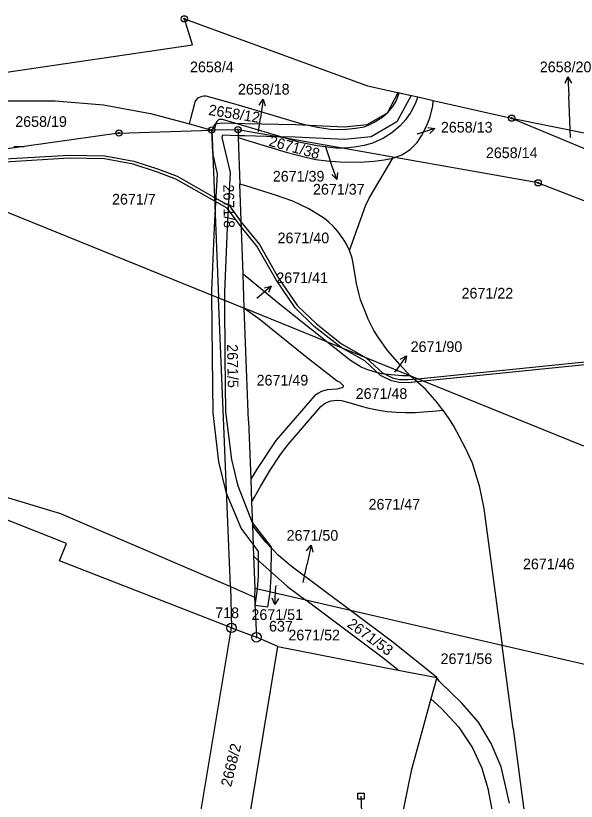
# Model space of a CAD drawing. Extents: x -755819 to -753140, y -1169796 to -1166000.
# Drawn here: x -754380.1 to -754290.9, y -1168245.5 to -1168120.5 of the extents above; entities that cross this region are included whole.
import ezdxf

# ---------------------------------------------------------------- set-up
doc = ezdxf.new("R2010")
doc.units = 0
for name, color, linetype in [('Vrstva 1', 7, 'Continuous'), ('Vrstva 12', 7, 'Continuous'), ('Vrstva 13', 7, 'Continuous'), ('Vrstva 16', 7, 'Continuous'), ('Vrstva 17', 7, 'Continuous'), ('Vrstva 18', 7, 'Continuous'), ('Vrstva 24', 7, 'Continuous'), ('Vrstva 26', 7, 'Continuous'), ('Vrstva 27', 7, 'Continuous'), ('Vrstva 4', 7, 'Continuous')]:
    doc.layers.add(name, color=color, linetype=linetype)

msp = doc.modelspace()

# ---------------------------------------------------------------- linework, layer by layer
at = {"layer": 'Vrstva 1'}
for p, q in [((-754319.59, -1168134.04), (-754319.11, -1168132.73)), ((-754382.31, -1168133.99), (-754373.85, -1168134)), ((-754373.85, -1168134), (-754366.18, -1168134.65)), ((-754351.68, -1168134.59), (-754351.55, -1168134.15)), ((-754351.55, -1168134.15), (-754351.36, -1168133.83)), ((-754351.36, -1168133.83), (-754351.07, -1168133.54)), ((-754351.07, -1168133.54), (-754350.74, -1168133.35)), ((-754350.74, -1168133.35), (-754350.45, -1168133.25)), ((-754350.45, -1168133.25), (-754350.18, -1168133.21)), ((-754350.18, -1168133.21), (-754349.89, -1168133.22)), ((-754349.89, -1168133.22), (-754344.72, -1168134.67)), ((-754320.12, -1168134.89), (-754319.59, -1168134.04)), ((-754316.15, -1168133.4), (-754316.57, -1168134.47)), ((-754313.75, -1168134.85), (-754313.67, -1168133.96)), ((-754366.18, -1168134.65), (-754358.7, -1168136.04)), ((-754352.27, -1168136.85), (-754351.68, -1168134.59)), ((-754344.72, -1168134.67), (-754334.58, -1168137.67)), ((-754320.92, -1168135.85), (-754320.12, -1168134.89)), ((-754316.57, -1168134.47), (-754317.25, -1168135.83)), ((-754314.23, -1168136.73), (-754313.75, -1168134.85)), ((-754358.7, -1168136.04), (-754352.46, -1168137.65)), ((-754323.07, -1168137.42), (-754321.87, -1168136.64)), ((-754321.87, -1168136.64), (-754320.92, -1168135.85)), ((-754317.25, -1168135.83), (-754318.07, -1168137.05)), ((-754352.46, -1168137.65), (-754352.27, -1168136.85)), ((-754352.46, -1168137.65), (-754348.93, -1168138.67)), ((-754348.29, -1168137.61), (-754348.54, -1168138.67)), ((-754348.24, -1168137.47), (-754348.29, -1168137.61)), ((-754348.14, -1168137.31), (-754348.24, -1168137.47)), ((-754348.02, -1168137.18), (-754348.14, -1168137.31)), ((-754347.9, -1168137.08), (-754348.02, -1168137.18)), ((-754347.72, -1168136.99), (-754347.9, -1168137.08)), ((-754347.47, -1168136.96), (-754347.72, -1168136.99)), ((-754347.23, -1168136.98), (-754347.47, -1168136.96)), ((-754337.18, -1168139.96), (-754347.23, -1168136.98)), ((-754334.58, -1168137.67), (-754332.1, -1168138.23)), ((-754324.67, -1168138.14), (-754323.87, -1168137.82)), ((-754323.87, -1168137.82), (-754323.07, -1168137.42)), ((-754318.07, -1168137.05), (-754318.92, -1168137.98)), ((-754315.53, -1168139.6), (-754314.69, -1168137.96)), ((-754314.69, -1168137.96), (-754314.23, -1168136.73)), ((-754301.2, -1168136.77), (-754285.23, -1168143.41)), ((-754363.71, -1168139.14), (-754378.79, -1168141.26)), ((-754363.71, -1168139.14), (-754348.93, -1168138.67)), ((-754348.93, -1168138.67), (-754347.83, -1168165.39)), ((-754348.54, -1168138.67), (-754348.93, -1168138.67)), ((-754344.74, -1168138.62), (-754348.54, -1168138.67)), ((-754337.18, -1168139.96), (-754344.74, -1168138.62)), ((-754344.74, -1168138.62), (-754344.7, -1168139.87)), ((-754332.1, -1168138.23), (-754329.7, -1168138.58)), ((-754329.7, -1168138.58), (-754327.51, -1168138.55)), ((-754327.51, -1168138.55), (-754326.01, -1168138.39)), ((-754326.01, -1168138.39), (-754324.67, -1168138.14)), ((-754320.24, -1168139.1), (-754321.57, -1168139.97)), ((-754318.92, -1168137.98), (-754320.24, -1168139.1)), ((-754344.7, -1168139.87), (-754342.88, -1168140.41)), ((-754344.7, -1168139.87), (-754344.44, -1168147.26)), ((-754342.88, -1168140.41), (-754337.11, -1168142.19)), ((-754328.18, -1168141.55), (-754337.18, -1168139.96)), ((-754335.08, -1168140.58), (-754337.18, -1168139.96)), ((-754321.57, -1168139.97), (-754323.32, -1168140.76)), ((-754316.24, -1168140.66), (-754315.53, -1168139.6)), ((-754378.79, -1168141.26), (-754385.44, -1168142.2)), ((-754380.44, -1168141.3), (-754378.79, -1168141.26)), ((-754332.16, -1168141.2), (-754335.08, -1168140.58)), ((-754329.2, -1168141.56), (-754332.16, -1168141.2)), ((-754328.18, -1168141.55), (-754329.2, -1168141.56)), ((-754327.77, -1168141.54), (-754328.18, -1168141.55)), ((-754319.78, -1168143.03), (-754328.18, -1168141.55)), ((-754326.21, -1168141.4), (-754327.77, -1168141.54)), ((-754324.68, -1168141.13), (-754326.21, -1168141.4)), ((-754323.32, -1168140.76), (-754324.68, -1168141.13)), ((-754317.35, -1168141.77), (-754316.24, -1168140.66)), ((-754337.11, -1168142.19), (-754333.81, -1168143.04)), ((-754319.78, -1168143.03), (-754318.66, -1168142.62)), ((-754318.66, -1168142.62), (-754317.35, -1168141.77)), ((-754333.81, -1168143.04), (-754332.35, -1168143.33)), ((-754332.35, -1168143.33), (-754330.6, -1168143.58)), ((-754330.6, -1168143.58), (-754328.54, -1168143.75)), ((-754328.54, -1168143.75), (-754326.84, -1168143.79)), ((-754326.84, -1168143.79), (-754324.61, -1168143.75)), ((-754324.61, -1168143.75), (-754323.08, -1168143.63)), ((-754323.85, -1168149.51), (-754320.11, -1168143.16)), ((-754323.08, -1168143.63), (-754321.49, -1168143.42)), ((-754321.49, -1168143.42), (-754320.11, -1168143.16)), ((-754320.11, -1168143.16), (-754319.78, -1168143.03)), ((-754296.97, -1168147.07), (-754319.78, -1168143.03)), ((-754399.92, -1168144.24), (-754347.83, -1168165.39)), ((-754343.53, -1168147.53), (-754344.44, -1168147.26)), ((-754343.94, -1168161.59), (-754344.44, -1168147.26)), ((-754338.78, -1168149.02), (-754343.53, -1168147.53)), ((-754296.97, -1168147.07), (-754280.8, -1168153.37)), ((-754336.04, -1168149.99), (-754338.78, -1168149.02)), ((-754333.48, -1168151.2), (-754336.04, -1168149.99)), ((-754324.46, -1168150.75), (-754323.85, -1168149.51)), ((-754330.99, -1168152.77), (-754333.48, -1168151.2)), ((-754326.98, -1168157.84), (-754324.46, -1168150.75)), ((-754330.29, -1168153.35), (-754330.99, -1168152.77)), ((-754329.61, -1168153.99), (-754330.29, -1168153.35)), ((-754328.87, -1168154.81), (-754329.61, -1168153.99)), ((-754328, -1168155.99), (-754328.87, -1168154.81)), ((-754327.47, -1168156.82), (-754328, -1168155.99)), ((-754326.98, -1168157.84), (-754327.47, -1168156.82)), ((-754326.58, -1168159.06), (-754326.98, -1168157.84)), ((-754326.37, -1168160.2), (-754326.58, -1168159.06)), ((-754325.89, -1168163.07), (-754326.37, -1168160.2)), ((-754338.39, -1168166.17), (-754343.94, -1168161.59)), ((-754343.75, -1168167.04), (-754343.94, -1168161.59)), ((-754325.48, -1168164.84), (-754325.89, -1168163.07)), ((-754345.95, -1168211.35), (-754347.83, -1168165.39)), ((-754347.83, -1168165.39), (-754347.17, -1168165.66)), ((-754325.24, -1168165.69), (-754325.48, -1168164.84)), ((-754347.17, -1168165.66), (-754343.75, -1168167.04)), ((-754330.62, -1168172.37), (-754338.39, -1168166.17)), ((-754324.95, -1168166.48), (-754325.24, -1168165.69)), ((-754324.47, -1168167.68), (-754324.95, -1168166.48)), ((-754330.62, -1168172.37), (-754343.75, -1168167.04)), ((-754343.75, -1168167.04), (-754341.46, -1168168.69)), ((-754343.06, -1168184.98), (-754343.75, -1168167.04)), ((-754324.01, -1168168.8), (-754324.47, -1168167.68)), ((-754341.46, -1168168.69), (-754333.72, -1168174.88)), ((-754323.15, -1168170.56), (-754324.01, -1168168.8)), ((-754322.32, -1168171.8), (-754323.15, -1168170.56)), ((-754317.32, -1168177.77), (-754330.62, -1168172.37)), ((-754326.86, -1168175.37), (-754330.62, -1168172.37)), ((-754320.92, -1168173.79), (-754322.32, -1168171.8)), ((-754319.74, -1168175.15), (-754320.92, -1168173.79)), ((-754333.72, -1168174.88), (-754328.98, -1168178.58)), ((-754325.15, -1168176.4), (-754326.86, -1168175.37)), ((-754319.04, -1168175.96), (-754319.74, -1168175.15)), ((-754324.08, -1168176.85), (-754325.15, -1168176.4)), ((-754317.32, -1168177.77), (-754319.04, -1168175.96)), ((-754323.24, -1168177.13), (-754324.08, -1168176.85)), ((-754321.87, -1168177.46), (-754323.24, -1168177.13)), ((-754320.44, -1168177.64), (-754321.87, -1168177.46)), ((-754318.58, -1168177.77), (-754320.44, -1168177.64)), ((-754317.32, -1168177.77), (-754318.58, -1168177.77)), ((-754289.7, -1168188.98), (-754317.32, -1168177.77)), ((-754314.89, -1168179.91), (-754317.32, -1168177.77)), ((-754328.98, -1168178.58), (-754328.55, -1168178.83)), ((-754328.55, -1168178.83), (-754328.16, -1168179.17)), ((-754328.16, -1168179.17), (-754328, -1168179.34)), ((-754331.44, -1168180.29), (-754332.02, -1168180.59)), ((-754330.58, -1168180.03), (-754331.44, -1168180.29)), ((-754329.79, -1168179.95), (-754330.58, -1168180.03)), ((-754329.03, -1168179.91), (-754329.79, -1168179.95)), ((-754328.45, -1168179.78), (-754329.03, -1168179.91)), ((-754328.18, -1168179.69), (-754328.45, -1168179.78)), ((-754328.03, -1168179.53), (-754328.18, -1168179.69)), ((-754328, -1168179.34), (-754328.03, -1168179.53)), ((-754313.06, -1168182.03), (-754314.89, -1168179.91)), ((-754332.55, -1168180.96), (-754338.73, -1168188.1)), ((-754332.02, -1168180.59), (-754332.55, -1168180.96)), ((-754329.92, -1168181.76), (-754329.08, -1168181.66)), ((-754329.08, -1168181.66), (-754328.28, -1168181.75)), ((-754336.76, -1168188.73), (-754331.58, -1168182.67)), ((-754331.58, -1168182.67), (-754330.82, -1168182.11)), ((-754330.82, -1168182.11), (-754329.92, -1168181.76)), ((-754328.28, -1168181.75), (-754326.39, -1168182.26)), ((-754326.39, -1168182.26), (-754325.14, -1168182.63)), ((-754325.14, -1168182.63), (-754323.9, -1168182.94)), ((-754323.9, -1168182.94), (-754322.6, -1168183.2)), ((-754312.15, -1168183.25), (-754313.06, -1168182.03)), ((-754322.6, -1168183.2), (-754321.03, -1168183.45)), ((-754321.03, -1168183.45), (-754319.52, -1168183.58)), ((-754319.52, -1168183.58), (-754318.15, -1168183.63)), ((-754318.15, -1168183.63), (-754316.57, -1168183.62)), ((-754316.57, -1168183.62), (-754315.22, -1168183.54)), ((-754315.22, -1168183.54), (-754313.08, -1168183.38)), ((-754313.08, -1168183.38), (-754312.15, -1168183.25)), ((-754312.15, -1168183.25), (-754311.2, -1168184.65)), ((-754343.06, -1168184.98), (-754342.72, -1168194.26)), ((-754311.2, -1168184.65), (-754310.4, -1168185.88)), ((-754310.4, -1168185.88), (-754308.58, -1168189.25)), ((-754338.73, -1168188.1), (-754341.77, -1168192.66)), ((-754337.96, -1168190.34), (-754336.76, -1168188.73)), ((-754339.61, -1168192.83), (-754337.96, -1168190.34)), ((-754308.58, -1168189.25), (-754307.46, -1168191.66)), ((-754307.46, -1168191.66), (-754306.35, -1168195.3)), ((-754341.77, -1168192.66), (-754342.72, -1168194.26)), ((-754341.15, -1168195.42), (-754339.61, -1168192.83)), ((-754342.72, -1168194.26), (-754342.59, -1168197.93)), ((-754342.13, -1168197.14), (-754341.15, -1168195.42)), ((-754306.35, -1168195.3), (-754305.6, -1168198.94)), ((-754384.53, -1168196.24), (-754373, -1168199.71)), ((-754342.59, -1168197.93), (-754342.13, -1168197.14)), ((-754342.59, -1168197.93), (-754342.45, -1168201.58)), ((-754372.07, -1168204.5), (-754385.48, -1168199.21)), ((-754305.6, -1168198.94), (-754304.86, -1168204.47)), ((-754373, -1168199.71), (-754367.22, -1168202.2)), ((-754342.45, -1168201.58), (-754342.28, -1168206.53)), ((-754341.83, -1168202.4), (-754342.45, -1168201.58)), ((-754367.22, -1168202.2), (-754345.95, -1168211.35)), ((-754340.34, -1168204.3), (-754341.83, -1168202.4)), ((-754373.15, -1168207.26), (-754372.07, -1168204.5)), ((-754338.3, -1168206.4), (-754340.34, -1168204.3)), ((-754304.86, -1168204.47), (-754302.71, -1168220.73)), ((-754342.28, -1168206.53), (-754342.09, -1168211.67)), ((-754342.28, -1168206.53), (-754336.82, -1168211.4)), ((-754336.29, -1168208.11), (-754338.3, -1168206.4)), ((-754345.79, -1168217.93), (-754373.15, -1168207.26)), ((-754326.84, -1168215.18), (-754336.29, -1168208.11)), ((-754345.95, -1168211.35), (-754342.15, -1168213.05)), ((-754345.95, -1168211.35), (-754345.79, -1168217.93)), ((-754342.09, -1168211.67), (-754342.15, -1168213.05)), ((-754333.95, -1168213.54), (-754342.09, -1168211.67)), ((-754336.82, -1168211.4), (-754333.95, -1168213.54)), ((-754342.15, -1168213.05), (-754341.81, -1168219.43)), ((-754326.84, -1168215.18), (-754333.95, -1168213.54)), ((-754321.41, -1168222.9), (-754333.95, -1168213.54)), ((-754320.32, -1168220.06), (-754326.84, -1168215.18)), ((-754302.71, -1168220.73), (-754326.84, -1168215.18)), ((-754352.79, -1168259.85), (-754345.79, -1168217.93)), ((-754338.39, -1168220.89), (-754341.81, -1168219.43)), ((-754316.38, -1168223.18), (-754320.32, -1168220.06)), ((-754345.13, -1168261.31), (-754338.39, -1168220.89)), ((-754338.39, -1168220.89), (-754319.26, -1168224.64)), ((-754300.97, -1168233.96), (-754302.71, -1168220.73)), ((-754285.02, -1168224.8), (-754302.71, -1168220.73)), ((-754319.26, -1168224.64), (-754321.41, -1168222.9)), ((-754313.12, -1168225.84), (-754316.38, -1168223.18)), ((-754319.26, -1168224.64), (-754313.12, -1168225.84)), ((-754313.12, -1168225.84), (-754314.05, -1168229.21)), ((-754312.67, -1168226.46), (-754313.12, -1168225.84)), ((-754309.1, -1168229.92), (-754312.67, -1168226.46)), ((-754314.05, -1168229.21), (-754317.19, -1168240.66)), ((-754312.38, -1168230.77), (-754314.05, -1168229.21)), ((-754306.48, -1168232.94), (-754309.1, -1168229.92)), ((-754312.38, -1168230.77), (-754309.65, -1168233.68)), ((-754304.43, -1168236.35), (-754306.48, -1168232.94)), ((-754309.65, -1168233.68), (-754307.43, -1168237)), ((-754300.97, -1168233.96), (-754296.06, -1168271.2)), ((-754302.87, -1168240.04), (-754304.43, -1168236.35)), ((-754307.43, -1168237), (-754305.94, -1168240.25)), ((-754305.94, -1168240.25), (-754304.96, -1168243.52)), ((-754301.53, -1168245.85), (-754302.87, -1168240.04)), ((-754317.19, -1168240.66), (-754323.74, -1168272.33)), ((-754304.96, -1168243.52), (-754304.26, -1168247.44))]:
    msp.add_line(p, q, dxfattribs=at)
at = {"layer": 'Vrstva 12'}
msp.add_line((-754325.18, -1168244.72), (-754312.91, -1168527.7), dxfattribs=at)
at = {"layer": 'Vrstva 13'}
for p, q in [((-754352, -1168125.1), (-754353.28, -1168120.96)), ((-754353.28, -1168120.96), (-754324.14, -1168131.6)), ((-754415.92, -1168134.53), (-754352, -1168125.1)), ((-754324.14, -1168131.6), (-754319.11, -1168132.73)), ((-754319.11, -1168132.73), (-754316.15, -1168133.4)), ((-754316.15, -1168133.4), (-754313.67, -1168133.96)), ((-754313.67, -1168133.96), (-754301.2, -1168136.77)), ((-754301.2, -1168136.77), (-754288.58, -1168139.32))]:
    msp.add_line(p, q, dxfattribs=at)
at = {"layer": 'Vrstva 16'}
for p, q in [((-754292.22, -1168130.2), (-754292.1, -1168133.2)), ((-754340.77, -1168133.76), (-754341.18, -1168136.73)), ((-754291.83, -1168139.87), (-754292.1, -1168133.2)), ((-754341.49, -1168138.91), (-754341.18, -1168136.73)), ((-754313.41, -1168138.44), (-754316.27, -1168139.33)), ((-754330.88, -1168141.19), (-754330.02, -1168143.7)), ((-754329.04, -1168146.54), (-754330.02, -1168143.7)), ((-754339.46, -1168163.53), (-754341.75, -1168165.46)), ((-754317.95, -1168174.61), (-754319.68, -1168177.06)), ((-754319.77, -1168177.19), (-754319.68, -1168177.06)), ((-754333.13, -1168204.78), (-754333.75, -1168207.72)), ((-754334.39, -1168210.72), (-754333.75, -1168207.72)), ((-754338.87, -1168214.22), (-754338.73, -1168211.22))]:
    msp.add_line(p, q, dxfattribs=at)
for points in [[(-754292.68, -1168131.22), (-754292.22, -1168130.2), (-754291.68, -1168131.18)], [(-754341.4, -1168134.68), (-754340.77, -1168133.76), (-754340.41, -1168134.82)], [(-754314.51, -1168138.26), (-754313.41, -1168138.44), (-754314.21, -1168139.22)], [(-754328.9, -1168145.43), (-754329.04, -1168146.54), (-754329.84, -1168145.75)], [(-754340.54, -1168163.79), (-754339.46, -1168163.53), (-754339.9, -1168164.55)], [(-754318.93, -1168175.14), (-754317.95, -1168174.61), (-754318.12, -1168175.72)], [(-754333.83, -1168205.66), (-754333.13, -1168204.78), (-754332.85, -1168205.87)], [(-754338.33, -1168213.24), (-754338.87, -1168214.22), (-754339.33, -1168213.19)]]:
    msp.add_lwpolyline(points, dxfattribs=at)
at = {"layer": 'Vrstva 24'}
for centre, radius in [((-754353.28, -1168120.96), 0.5), ((-754353.28, -1168120.96), 0.1), ((-754301.2, -1168136.77), 0.5), ((-754301.2, -1168136.77), 0.1), ((-754363.71, -1168139.14), 0.5), ((-754363.71, -1168139.14), 0.1), ((-754348.93, -1168138.67), 0.5), ((-754348.93, -1168138.67), 0.1), ((-754344.74, -1168138.62), 0.5), ((-754344.74, -1168138.62), 0.1), ((-754296.97, -1168147.07), 0.5), ((-754296.97, -1168147.07), 0.1), ((-754345.79, -1168217.93), 0.75), ((-754345.79, -1168217.93), 0.1), ((-754341.81, -1168219.43), 0.75), ((-754341.81, -1168219.43), 0.1)]:
    msp.add_circle(centre, radius, dxfattribs=at)
at = {"layer": 'Vrstva 26'}
msp.add_lwpolyline([(-754325.68, -1168244.22), (-754324.68, -1168244.22), (-754324.68, -1168245.22), (-754325.68, -1168245.22)], close=True, dxfattribs=at)
at = {"layer": 'Vrstva 27'}
for p, q in [((-754320.97, -1168135.91), (-754319.24, -1168132.71)), ((-754319.24, -1168132.71), (-754317.21, -1168133.16)), ((-754317.21, -1168133.16), (-754319.47, -1168137.37)), ((-754324.21, -1168137.78), (-754320.97, -1168135.91)), ((-754348.93, -1168138.67), (-754348.38, -1168137.66)), ((-754348.38, -1168137.66), (-754347.36, -1168137.49)), ((-754347.36, -1168137.49), (-754343.68, -1168137.61)), ((-754343.68, -1168137.61), (-754335.59, -1168137.8)), ((-754335.59, -1168137.8), (-754327.84, -1168138.17)), ((-754327.84, -1168138.17), (-754324.21, -1168137.78)), ((-754319.47, -1168137.37), (-754323.57, -1168139.72)), ((-754348.78, -1168142.32), (-754348.93, -1168138.67)), ((-754347.22, -1168139.49), (-754347.3, -1168139.84)), ((-754347.3, -1168139.84), (-754346, -1168145.43)), ((-754344.71, -1168139.58), (-754347.22, -1168139.49)), ((-754343.74, -1168139.61), (-754344.71, -1168139.58)), ((-754338.44, -1168139.73), (-754343.74, -1168139.61)), ((-754335.67, -1168139.8), (-754338.44, -1168139.73)), ((-754327.78, -1168140.17), (-754335.67, -1168139.8)), ((-754323.57, -1168139.72), (-754327.78, -1168140.17)), ((-754381.88, -1168143.27), (-754371.64, -1168142.66)), ((-754371.64, -1168142.66), (-754365.95, -1168142.75)), ((-754365.95, -1168142.75), (-754361.33, -1168143.64)), ((-754348.02, -1168145.61), (-754348.78, -1168142.32)), ((-754371.63, -1168143.16), (-754381.87, -1168143.77)), ((-754366.01, -1168143.25), (-754371.63, -1168143.16)), ((-754361.45, -1168144.12), (-754366.01, -1168143.25)), ((-754357.55, -1168145.35), (-754361.45, -1168144.12)), ((-754361.33, -1168143.64), (-754357.39, -1168144.87)), ((-754354.63, -1168146.47), (-754357.55, -1168145.35)), ((-754357.39, -1168144.87), (-754354.41, -1168146.01)), ((-754346, -1168145.43), (-754346.49, -1168154.22)), ((-754348.46, -1168149.98), (-754354.63, -1168146.47)), ((-754354.41, -1168146.01), (-754348.49, -1168149.39)), ((-754348.38, -1168152.1), (-754348.02, -1168145.61)), ((-754348.49, -1168149.39), (-754346.13, -1168150.74)), ((-754346.47, -1168151.12), (-754348.46, -1168149.98)), ((-754344.2, -1168154.14), (-754346.47, -1168151.12)), ((-754346.13, -1168150.74), (-754344.23, -1168153.31)), ((-754348.49, -1168154.12), (-754348.38, -1168152.1)), ((-754348.9, -1168164.32), (-754348.49, -1168154.12)), ((-754346.49, -1168154.22), (-754346.9, -1168164.36)), ((-754344.23, -1168153.31), (-754341.35, -1168156.87)), ((-754341.77, -1168157.15), (-754344.2, -1168154.14)), ((-754338.7, -1168162.51), (-754341.77, -1168157.15)), ((-754341.35, -1168156.87), (-754338.28, -1168162.25)), ((-754335.64, -1168166.97), (-754338.7, -1168162.51)), ((-754338.28, -1168162.25), (-754335.26, -1168166.65)), ((-754348.9, -1168164.96), (-754348.9, -1168164.32)), ((-754348.83, -1168174.84), (-754348.9, -1168164.96)), ((-754346.9, -1168164.36), (-754346.89, -1168165.77)), ((-754346.89, -1168165.77), (-754346.83, -1168174.82)), ((-754335.26, -1168166.65), (-754332.28, -1168169.54)), ((-754332.61, -1168169.92), (-754335.64, -1168166.97)), ((-754328.32, -1168173.3), (-754332.61, -1168169.92)), ((-754332.28, -1168169.54), (-754328.25, -1168172.72)), ((-754328.25, -1168172.72), (-754324.35, -1168174.91)), ((-754324.54, -1168175.42), (-754328.32, -1168173.3)), ((-754348.73, -1168183.69), (-754348.83, -1168174.84)), ((-754346.83, -1168174.82), (-754346.73, -1168183.55)), ((-754322.05, -1168177.74), (-754324.54, -1168175.42)), ((-754324.35, -1168174.91), (-754321.77, -1168177.32)), ((-754316.13, -1168178.25), (-754287.74, -1168175.36)), ((-754287.68, -1168175.86), (-754315.15, -1168178.65)), ((-754320.32, -1168178.6), (-754322.05, -1168177.74)), ((-754321.77, -1168177.32), (-754320.16, -1168178.12)), ((-754319.09, -1168178.87), (-754320.32, -1168178.6)), ((-754320.16, -1168178.12), (-754319.03, -1168178.37)), ((-754317.66, -1168178.9), (-754319.09, -1168178.87)), ((-754319.03, -1168178.37), (-754317.68, -1168178.4)), ((-754317.68, -1168178.4), (-754316.13, -1168178.25)), ((-754315.15, -1168178.65), (-754317.66, -1168178.9)), ((-754347.78, -1168191.5), (-754348.73, -1168183.69)), ((-754346.73, -1168183.55), (-754345.8, -1168191.14)), ((-754346.56, -1168196.48), (-754347.78, -1168191.5)), ((-754345.8, -1168191.14), (-754344.82, -1168195.15)), ((-754344.82, -1168195.15), (-754342.47, -1168201.15)), ((-754344.27, -1168202.04), (-754346.56, -1168196.48)), ((-754342.47, -1168201.15), (-754339.48, -1168205.09)), ((-754342.35, -1168204.6), (-754344.27, -1168202.04)), ((-754341.48, -1168205.75), (-754342.35, -1168204.6)), ((-754339.48, -1168205.09), (-754339.51, -1168209.79)), ((-754341.51, -1168209.71), (-754341.48, -1168205.75)), ((-754341.66, -1168211.77), (-754341.51, -1168209.71)), ((-754339.51, -1168209.79), (-754339.68, -1168212.23)), ((-754342.01, -1168214.36), (-754341.68, -1168212.14)), ((-754341.68, -1168212.14), (-754341.66, -1168211.77)), ((-754339.68, -1168212.23), (-754340.03, -1168214.65)), ((-754340.03, -1168214.65), (-754342.01, -1168214.36))]:
    msp.add_line(p, q, dxfattribs=at)
at = {"layer": 'Vrstva 4'}
msp.add_line((-754345.79, -1168217.93), (-754341.81, -1168219.43), dxfattribs=at)

# ---------------------------------------------------------------- texts
at = {"layer": 'Vrstva 16'}
for s, p in [('2658/20', (-754296.71, -1168129.46)), ('2658/18', (-754344.76, -1168133.02)), ('2658/19', (-754380.21, -1168138.16)), ('2658/13', (-754312.45, -1168139.07)), ('2671/37', (-754332.81, -1168148.94)), ('2671/41', (-754338.65, -1168163.04)), ('2671/90', (-754317.27, -1168174)), ('2671/50', (-754337.01, -1168204.05)), ('2671/51', (-754342.61, -1168216.66))]:
    msp.add_text(s, height=1.7, dxfattribs=at).set_placement(p)
at = {"layer": 'Vrstva 17'}
for s, p in [('718', (-754348.37, -1168216.37)), ('637', (-754339.81, -1168218.51))]:
    msp.add_text(s, height=1.7, dxfattribs=at).set_placement(p)
at = {"layer": 'Vrstva 18'}
for s, height, p in [('2658/4', 1.7, (-754352.39, -1168129.46)), ('2658/18', 0.1, (-754341.48, -1168138.91)), ('2658/13', 0.1, (-754316.26, -1168139.33)), ('2658/20', 0.1, (-754291.82, -1168139.87)), ('2671/37', 0.1, (-754330.87, -1168141.19)), ('2658/14', 1.7, (-754305.29, -1168143.14)), ('2671/39', 1.7, (-754339.21, -1168146.87)), ('2671/7', 1.7, (-754364.8, -1168150.52)), ('2671/40', 1.7, (-754338.45, -1168156.69)), ('2671/22', 1.7, (-754309.16, -1168165.49)), ('2671/41', 0.1, (-754341.75, -1168165.46)), ('2671/49', 1.7, (-754341.79, -1168179.34)), ('2671/90', 0.1, (-754319.76, -1168177.19)), ('2671/48', 1.7, (-754326.02, -1168181.47)), ('2671/47', 1.7, (-754323.97, -1168199.1)), ('2671/46', 1.7, (-754299.39, -1168208.6)), ('2671/51', 0.1, (-754338.72, -1168211.22)), ('2671/50', 0.1, (-754334.38, -1168210.72)), ('2671/52', 1.7, (-754336.73, -1168219.92)), ('2671/56', 1.7, (-754312.5, -1168223.68))]:
    msp.add_text(s, height=height, dxfattribs=at).set_placement(p)
for s, rotation, p in [('2658/12', 350.9939, (-754349.53, -1168136.25)), ('2671/38', 344.6914, (-754339.95, -1168141.15)), ('2671/8', 270.8944, (-754347.1, -1168147.34)), ('2671/5', 270.8944, (-754346.49, -1168172.77)), ('2671/53', 324.0076, (-754327.51, -1168217.63)), ('2668/2', 76.4899, (-754345.85, -1168243.33))]:
    msp.add_text(s, height=1.7, rotation=rotation, dxfattribs=at).set_placement(p)

doc.saveas('drawing.dxf')
